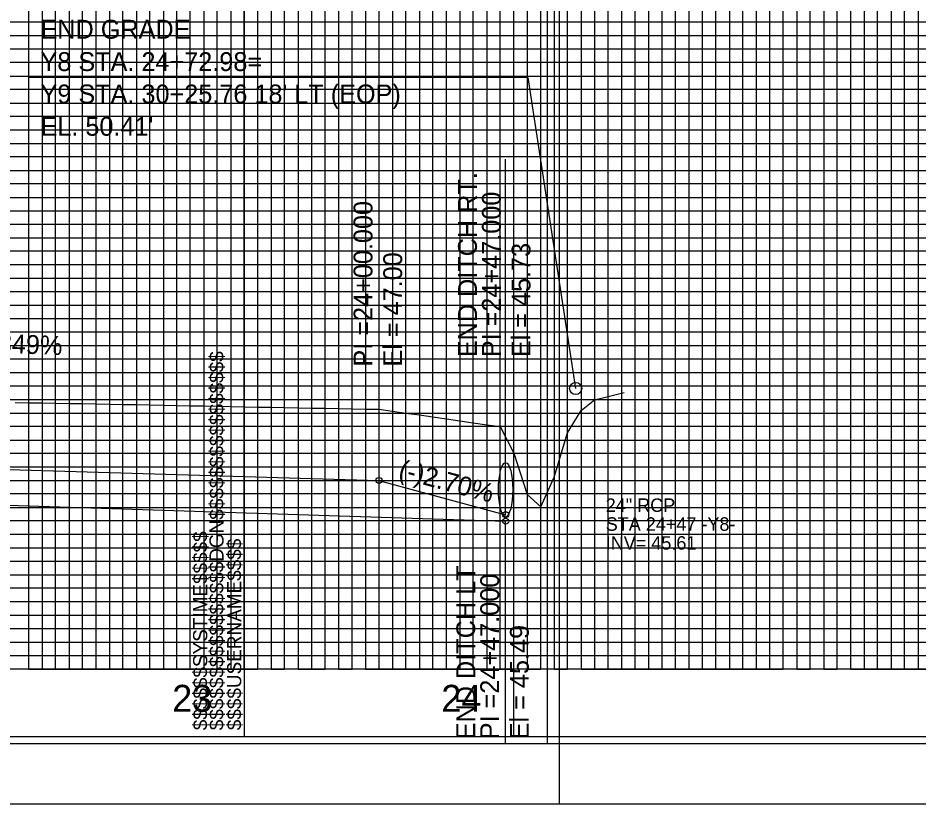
# Model space of a CAD drawing. Extents: x 2345490 to 2436403, y 465165 to 573888.
# Drawn here: x 2383032.9 to 2383366.8, y 540974.5 to 541266 of the extents above; entities that cross this region are included whole.
import ezdxf

# ---------------------------------------------------------------- set-up
doc = ezdxf.new("R2010")
doc.units = 0
for name, color, linetype in [('Exist Vertical Profile Horizontal Axis Label Major', 7, 'Continuous'), ('Old_Level_1', 7, 'Continuous'), ('Old_Level_18', 7, 'Continuous'), ('Old_Level_2', 7, 'Continuous'), ('Old_Level_3', 7, 'Continuous'), ('Old_Level_40', 7, 'Continuous'), ('Old_Level_41', 7, 'Continuous'), ('Old_Level_42', 7, 'Continuous'), ('Old_Level_43', 7, 'Continuous'), ('Old_Level_50', 7, 'Continuous'), ('Old_Level_51', 7, 'Continuous')]:
    doc.layers.add(name, color=color, linetype=linetype)

msp = doc.modelspace()

# ---------------------------------------------------------------- linework, layer by layer
at = {"layer": 'Old_Level_1'}
msp.add_lwpolyline([(2383031.7988, 541123.441), (2383036.7988, 541123.35714), (2383041.7988, 541123.27083), (2383046.7988, 541123.1821), (2383051.7988, 541123.091), (2383056.7988, 541122.99758), (2383061.7988, 541122.90186), (2383066.7988, 541122.80938), (2383071.7988, 541122.72287), (2383076.7988, 541122.63529), (2383081.7988, 541122.54668), (2383086.7988, 541122.45707), (2383091.7988, 541122.35847), (2383096.7988, 541122.23957), (2383101.7988, 541122.13262), (2383106.7988, 541122.03737), (2383111.7988, 541121.94212), (2383116.7988, 541121.84688), (2383121.7988, 541121.75163), (2383126.7988, 541121.65638), (2383131.7988, 541121.56114), (2383136.7988, 541121.46589), (2383141.7988, 541121.37064), (2383146.7988, 541121.2754), (2383151.7988, 541121.18015), (2383156.7988, 541121.0849), (2383161.7988, 541120.98965), (2383166.7988, 541120.89441), (2383171.7988, 541120.24181), (2383176.7988, 541119.51729), (2383181.7988, 541118.79276), (2383186.7988, 541118.06824), (2383191.7988, 541117.34372), (2383196.7988, 541116.61919), (2383201.7988, 541115.89467), (2383206.7988, 541115.17015), (2383211.7988, 541114.57352), (2383216.7988, 541104.6758), (2383221.7988, 541089.28992), (2383226.7988, 541084.70339), (2383231.7988, 541095.7072), (2383236.7988, 541112.14277), (2383241.7988, 541120.4894), (2383246.7988, 541124.38886), (2383251.7988, 541125.6911), (2383256.7988, 541126.94345), (2383257.7788, 541127.17918)], dxfattribs=at)
at = {"layer": 'Old_Level_18'}
msp.add_line((2383116.79875, 540999.5045), (2383116.79875, 540999.5045), dxfattribs=at)
msp.add_line((2383116.79875, 540999.5045), (2383116.79875, 540999.5045), dxfattribs=at)
for points in [[(2383216.79875, 542049.5045), (2381716.79875, 542049.5045), (2381716.79875, 540999.5045), (2383216.79875, 540999.5045)], [(2384616.79875, 542049.5045), (2383116.79875, 542049.5045), (2383116.79875, 540999.5045), (2384616.79875, 540999.5045)]]:
    msp.add_lwpolyline(points, close=True, dxfattribs=at)
at = {"layer": 'Old_Level_2'}
for q in [(2383036.88355, 541243.91325), (2383239.77875, 541128.6045)]:
    msp.add_line((2383222.04055, 541243.91325), q, dxfattribs=at)
msp.add_circle((2383239.77875, 541128.6045), 2.25, dxfattribs=at)
at = {"layer": 'Old_Level_3'}
for p, q in [((2383213.7988, 541081.8045), (2383213.7988, 541213.67542)), ((2383166.7988, 541210.1541), (2383166.7988, 541094.5045)), ((2382316.79909, 541108.4045), (2383213.7988, 541079.4045)), ((2382866.7988, 541103.5045), (2383166.7988, 541094.5045)), ((2383166.7988, 541094.5045), (2383213.7988, 541081.8045)), ((2383213.7988, 540997.24227), (2383213.7988, 541079.4045))]:
    msp.add_line(p, q, dxfattribs=at)
for centre in [(2383166.7988, 541094.5045), (2383213.7988, 541081.8045), (2383213.7988, 541079.4045)]:
    msp.add_circle(centre, 1.12602, dxfattribs=at)
msp.add_ellipse((2383213.7988, 541091.1045), major_axis=(0, -10), ratio=0.264816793, dxfattribs=at)
at = {"layer": 'Old_Level_40'}
msp.add_line((2383116.79875, 540999.5045), (2383116.79875, 540999.5045), dxfattribs=at)
msp.add_line((2383116.79875, 540999.5045), (2383116.79875, 540999.5045), dxfattribs=at)
msp.add_line((2383116.79875, 540999.5045), (2383116.79875, 540999.5045), dxfattribs=at)
msp.add_line((2383116.79875, 540999.5045), (2383116.79875, 540999.5045), dxfattribs=at)
at = {"layer": 'Old_Level_41'}
for p, q in [((2383216.79875, 541024.5045), (2381716.79875, 541024.5045)), ((2384616.79875, 541024.5045), (2383116.79875, 541024.5045))]:
    msp.add_line(p, q, dxfattribs=at)
for points in [[(2383116.79875, 542049.5045), (2383166.79875, 542049.5045), (2383166.79875, 541024.5045), (2383216.79875, 541024.5045), (2383216.79875, 542049.5045), (2383266.79875, 542049.5045), (2383266.79875, 541024.5045), (2383316.79875, 541024.5045), (2383316.79875, 542049.5045), (2383366.79875, 542049.5045), (2383366.79875, 541024.5045), (2383416.79875, 541024.5045), (2383416.79875, 542049.5045), (2383466.79875, 542049.5045), (2383466.79875, 541024.5045), (2383516.79875, 541024.5045), (2383516.79875, 542049.5045), (2383566.79875, 542049.5045), (2383566.79875, 541024.5045), (2383616.79875, 541024.5045), (2383616.79875, 542049.5045), (2383666.79875, 542049.5045), (2383666.79875, 541024.5045), (2383716.79875, 541024.5045)], [(2383191.79875, 541024.5045), (2383191.79875, 542049.5045), (2383241.79875, 542049.5045), (2383241.79875, 541024.5045), (2383291.79875, 541024.5045), (2383291.79875, 542049.5045), (2383341.79875, 542049.5045), (2383341.79875, 541024.5045), (2383391.79875, 541024.5045), (2383391.79875, 542049.5045), (2383441.79875, 542049.5045), (2383441.79875, 541024.5045), (2383491.79875, 541024.5045), (2383491.79875, 542049.5045), (2383541.79875, 542049.5045), (2383541.79875, 541024.5045), (2383591.79875, 541024.5045), (2383591.79875, 542049.5045), (2383641.79875, 542049.5045), (2383641.79875, 541024.5045), (2383691.79875, 541024.5045), (2383691.79875, 542049.5045), (2383741.79875, 542049.5045)], [(2383041.79875, 541911.9545), (2383041.79875, 541024.5045), (2383091.79875, 541024.5045), (2383091.79875, 541911.9545)], [(2383141.79875, 541911.9545), (2383141.79875, 541024.5045)], [(2383216.79875, 541249.5045), (2381716.79875, 541249.5045), (2381716.79875, 541199.5045), (2383216.79875, 541199.5045)], [(2384616.79875, 541249.5045), (2383116.79875, 541249.5045), (2383116.79875, 541199.5045), (2384616.79875, 541199.5045)], [(2383216.79875, 541149.5045), (2381716.79875, 541149.5045), (2381716.79875, 541099.5045), (2383216.79875, 541099.5045)], [(2384616.79875, 541149.5045), (2383116.79875, 541149.5045), (2383116.79875, 541099.5045), (2384616.79875, 541099.5045)], [(2383216.79875, 541074.5045), (2381716.79875, 541074.5045), (2381716.79875, 541124.5045), (2383216.79875, 541124.5045)], [(2384616.79875, 541074.5045), (2383116.79875, 541074.5045), (2383116.79875, 541124.5045), (2384616.79875, 541124.5045)], [(2383216.79875, 541049.5045), (2381716.79875, 541049.5045)], [(2384616.79875, 541049.5045), (2383116.79875, 541049.5045)], [(2383154.29875, 540999.5045), (2383154.29875, 540999.5045)]]:
    msp.add_lwpolyline(points, dxfattribs=at)
at = {"layer": 'Old_Level_42'}
for points in [[(2383066.79875, 541911.9545), (2383066.79875, 541024.5045), (2383116.79875, 541024.5045), (2383116.79875, 541911.9545)], [(2383166.79875, 541911.9545), (2383166.79875, 541024.5045), (2383216.79875, 541024.5045)], [(2383216.79875, 541174.5045), (2381716.79875, 541174.5045), (2381716.79875, 541224.5045), (2383216.79875, 541224.5045)], [(2384616.79875, 541174.5045), (2383116.79875, 541174.5045), (2383116.79875, 541224.5045), (2384616.79875, 541224.5045)]]:
    msp.add_lwpolyline(points, dxfattribs=at)
at = {"layer": 'Old_Level_43'}
for points in [[(2383171.79875, 542049.5045), (2383171.79875, 541024.5045), (2383176.79875, 541024.5045), (2383176.79875, 542049.5045)], [(2383181.79875, 542049.5045), (2383181.79875, 541024.5045), (2383186.79875, 541024.5045), (2383186.79875, 542049.5045)], [(2383196.79875, 542049.5045), (2383196.79875, 541024.5045), (2383201.79875, 541024.5045), (2383201.79875, 542049.5045)], [(2383206.79875, 542049.5045), (2383206.79875, 541024.5045), (2383211.79875, 541024.5045), (2383211.79875, 542049.5045)], [(2383221.79875, 542049.5045), (2383221.79875, 541024.5045), (2383226.79875, 541024.5045), (2383226.79875, 542049.5045)], [(2383231.79875, 542049.5045), (2383231.79875, 541024.5045), (2383236.79875, 541024.5045), (2383236.79875, 542049.5045)], [(2383246.79875, 542049.5045), (2383246.79875, 541024.5045), (2383251.79875, 541024.5045), (2383251.79875, 542049.5045)], [(2383256.79875, 542049.5045), (2383256.79875, 541024.5045), (2383261.79875, 541024.5045), (2383261.79875, 542049.5045)], [(2383271.79875, 542049.5045), (2383271.79875, 541024.5045), (2383276.79875, 541024.5045), (2383276.79875, 542049.5045)], [(2383281.79875, 542049.5045), (2383281.79875, 541024.5045), (2383286.79875, 541024.5045), (2383286.79875, 542049.5045)], [(2383296.79875, 542049.5045), (2383296.79875, 541024.5045), (2383301.79875, 541024.5045), (2383301.79875, 542049.5045)], [(2383306.79875, 542049.5045), (2383306.79875, 541024.5045), (2383311.79875, 541024.5045), (2383311.79875, 542049.5045)], [(2383321.79875, 542049.5045), (2383321.79875, 541024.5045), (2383326.79875, 541024.5045), (2383326.79875, 542049.5045)], [(2383331.79875, 541024.5045), (2383336.79875, 541024.5045), (2383336.79875, 542049.5045)], [(2383331.79875, 542049.5045), (2383331.79875, 541024.5045)], [(2383346.79875, 542049.5045), (2383346.79875, 541024.5045), (2383351.79875, 541024.5045), (2383351.79875, 542049.5045)], [(2383356.79875, 542049.5045), (2383356.79875, 541024.5045), (2383361.79875, 541024.5045), (2383361.79875, 542049.5045)], [(2383036.79875, 541911.9545), (2383036.79875, 541024.5045), (2383046.79875, 541024.5045), (2383046.79875, 541911.9545)], [(2383051.79875, 541911.9545), (2383051.79875, 541024.5045), (2383056.79875, 541024.5045), (2383056.79875, 541911.9545)], [(2383061.79875, 541911.9545), (2383061.79875, 541024.5045), (2383071.79875, 541024.5045), (2383071.79875, 541911.9545)], [(2383076.79875, 541911.9545), (2383076.79875, 541024.5045), (2383081.79875, 541024.5045), (2383081.79875, 541911.9545)], [(2383086.79875, 541911.9545), (2383086.79875, 541024.5045), (2383096.79875, 541024.5045), (2383096.79875, 541911.9545)], [(2383101.79875, 541911.9545), (2383101.79875, 541024.5045)], [(2383101.79875, 541024.5045), (2383106.79875, 541024.5045), (2383106.79875, 541911.9545)], [(2383111.79875, 541911.9545), (2383111.79875, 541024.5045), (2383121.79875, 541024.5045), (2383121.79875, 541911.9545)], [(2383126.79875, 541911.9545), (2383126.79875, 541024.5045), (2383131.79875, 541024.5045), (2383131.79875, 541911.9545)], [(2383136.79875, 541911.9545), (2383136.79875, 541024.5045), (2383146.79875, 541024.5045), (2383146.79875, 541911.9545)], [(2383151.79875, 541911.9545), (2383151.79875, 541024.5045), (2383156.79875, 541024.5045), (2383156.79875, 541911.9545)], [(2383161.79875, 541911.9545), (2383161.79875, 541024.5045), (2383171.79875, 541024.5045)], [(2383166.79875, 541264.5045), (2381766.79875, 541264.5045), (2381766.79875, 541259.5045), (2383166.79875, 541259.5045)], [(2384566.79875, 541264.5045), (2383166.79875, 541264.5045), (2383166.79875, 541259.5045), (2384566.79875, 541259.5045)], [(2383166.79875, 541254.5045), (2381766.79875, 541254.5045), (2381766.79875, 541244.5045), (2383166.79875, 541244.5045)], [(2384566.79875, 541254.5045), (2383166.79875, 541254.5045), (2383166.79875, 541244.5045), (2384566.79875, 541244.5045)], [(2383166.79875, 541239.5045), (2381766.79875, 541239.5045), (2381766.79875, 541234.5045), (2383166.79875, 541234.5045)], [(2384566.79875, 541239.5045), (2383166.79875, 541239.5045), (2383166.79875, 541234.5045), (2384566.79875, 541234.5045)], [(2383166.79875, 541229.5045), (2381766.79875, 541229.5045)], [(2384566.79875, 541229.5045), (2383166.79875, 541229.5045)], [(2381766.79875, 541219.5045), (2383166.79875, 541219.5045)], [(2383166.79875, 541219.5045), (2384566.79875, 541219.5045)], [(2383166.79875, 541214.5045), (2381766.79875, 541214.5045), (2381766.79875, 541209.5045), (2383166.79875, 541209.5045)], [(2384566.79875, 541214.5045), (2383166.79875, 541214.5045), (2383166.79875, 541209.5045), (2384566.79875, 541209.5045)], [(2383166.79875, 541204.5045), (2381766.79875, 541204.5045)], [(2384566.79875, 541204.5045), (2383166.79875, 541204.5045)], [(2381766.79875, 541194.5045), (2383166.79875, 541194.5045)], [(2383166.79875, 541194.5045), (2384566.79875, 541194.5045)], [(2383166.79875, 541189.5045), (2381766.79875, 541189.5045), (2381766.79875, 541184.5045), (2383166.79875, 541184.5045)], [(2384566.79875, 541189.5045), (2383166.79875, 541189.5045), (2383166.79875, 541184.5045), (2384566.79875, 541184.5045)], [(2383166.79875, 541179.5045), (2381766.79875, 541179.5045), (2381766.79875, 541169.5045), (2383166.79875, 541169.5045)], [(2384566.79875, 541179.5045), (2383166.79875, 541179.5045), (2383166.79875, 541169.5045), (2384566.79875, 541169.5045)], [(2383166.79875, 541164.5045), (2381766.79875, 541164.5045), (2381766.79875, 541159.5045), (2383166.79875, 541159.5045)], [(2384566.79875, 541164.5045), (2383166.79875, 541164.5045), (2383166.79875, 541159.5045), (2384566.79875, 541159.5045)], [(2383166.79875, 541154.5045), (2381766.79875, 541154.5045), (2381766.79875, 541144.5045), (2383166.79875, 541144.5045)], [(2384566.79875, 541154.5045), (2383166.79875, 541154.5045), (2383166.79875, 541144.5045), (2384566.79875, 541144.5045)], [(2383166.79875, 541139.5045), (2381766.79875, 541139.5045), (2381766.79875, 541134.5045), (2383166.79875, 541134.5045)], [(2384566.79875, 541139.5045), (2383166.79875, 541139.5045), (2383166.79875, 541134.5045), (2384566.79875, 541134.5045)], [(2383166.79875, 541129.5045), (2381766.79875, 541129.5045), (2381766.79875, 541119.5045), (2383166.79875, 541119.5045)], [(2384566.79875, 541129.5045), (2383166.79875, 541129.5045), (2383166.79875, 541119.5045), (2384566.79875, 541119.5045)], [(2383166.79875, 541114.5045), (2381766.79875, 541114.5045), (2381766.79875, 541109.5045), (2383166.79875, 541109.5045)], [(2384566.79875, 541114.5045), (2383166.79875, 541114.5045), (2383166.79875, 541109.5045), (2384566.79875, 541109.5045)], [(2383166.79875, 541104.5045), (2381766.79875, 541104.5045), (2381766.79875, 541094.5045), (2383166.79875, 541094.5045)], [(2384566.79875, 541104.5045), (2383166.79875, 541104.5045), (2383166.79875, 541094.5045), (2384566.79875, 541094.5045)], [(2383166.79875, 541089.5045), (2381766.79875, 541089.5045), (2381766.79875, 541084.5045), (2383166.79875, 541084.5045)], [(2384566.79875, 541089.5045), (2383166.79875, 541089.5045), (2383166.79875, 541084.5045), (2384566.79875, 541084.5045)], [(2383166.79875, 541079.5045), (2381766.79875, 541079.5045), (2381766.79875, 541069.5045), (2383166.79875, 541069.5045)], [(2384566.79875, 541079.5045), (2383166.79875, 541079.5045), (2383166.79875, 541069.5045), (2384566.79875, 541069.5045)], [(2383166.79875, 541064.5045), (2381766.79875, 541064.5045), (2381766.79875, 541059.5045), (2383166.79875, 541059.5045)], [(2384566.79875, 541064.5045), (2383166.79875, 541064.5045), (2383166.79875, 541059.5045), (2384566.79875, 541059.5045)], [(2383166.79875, 541054.5045), (2381766.79875, 541054.5045), (2381766.79875, 541044.5045), (2383166.79875, 541044.5045)], [(2384566.79875, 541054.5045), (2383166.79875, 541054.5045), (2383166.79875, 541044.5045), (2384566.79875, 541044.5045)], [(2383166.79875, 541039.5045), (2381766.79875, 541039.5045), (2381766.79875, 541034.5045), (2383166.79875, 541034.5045)], [(2384566.79875, 541039.5045), (2383166.79875, 541039.5045), (2383166.79875, 541034.5045), (2384566.79875, 541034.5045)], [(2383166.79875, 541029.5045), (2381766.79875, 541029.5045)], [(2384566.79875, 541029.5045), (2383166.79875, 541029.5045)]]:
    msp.add_lwpolyline(points, dxfattribs=at)
at = {"layer": 'Old_Level_50'}
for points in [[(2383229.29875, 542052.0545), (2381562.79875, 542052.0545), (2381562.79875, 540996.9545), (2383229.29875, 540996.9545)], [(2384629.29875, 542052.0545), (2382962.79875, 542052.0545), (2382962.79875, 540996.9545), (2384629.29875, 540996.9545)]]:
    msp.add_lwpolyline(points, close=True, dxfattribs=at)
at = {"layer": 'Old_Level_51'}
for points in [[(2383233.79875, 542074.5045), (2381549.79875, 542074.5045), (2381549.79875, 540974.5045), (2383233.79875, 540974.5045)], [(2384633.79875, 542074.5045), (2382949.79875, 542074.5045), (2382949.79875, 540974.5045), (2384633.79875, 540974.5045)]]:
    msp.add_lwpolyline(points, close=True, dxfattribs=at)

# ---------------------------------------------------------------- texts
at = {"layer": 'Exist Vertical Profile Horizontal Axis Label Major'}
for s, p in [('23', (2383090.09389, 541008.69864)), ('24', (2383189.93631, 541008.69864))]:
    msp.add_text(s, height=10.000001, dxfattribs=at).set_placement(p)
at = {"layer": 'Old_Level_2'}
for s, height, p in [('END GRADE', 7.000001, (2383041.2238, 541258.36625)), ('Y8 STA. 24+72.98=', 7.0000005, (2383041.2238, 541246.36625)), ("Y9 STA. 30+25.76 18' LT (EOP)", 7.0000005, (2383041.2238, 541234.36625)), ("EL. 50.41' ", 7.0000005, (2383041.2238, 541222.36625))]:
    msp.add_text(s, height=height, dxfattribs=at).set_placement(p)
msp.add_text('(-)0.3849%', height=7, rotation=357.7471697, dxfattribs=at).set_placement((2383002.94472, 541142.81846))
at = {"layer": 'Old_Level_3'}
for s, height, rotation, p in [('END DITCH RT.', 7.0000005, 90, (2383203.14605, 541140.21463)), ('PI =24+47.000', 7.0000005, 90, (2383212.01995, 541140.21463)), ('PI =24+00.000', 7.0000005, 90, (2383164.3938, 541136.7485)), ('El = 45.73', 7.000001, 90, (2383223.01995, 541140.21463)), ('El = 47.00', 7.000001, 90, (2383175.3938, 541136.7485)), ('(-)2.70%', 7.000001, 344.8790632, (2383173.65627, 541095.56937)), ('END DITCH LT', 7.0000005, 90, (2383202.5199, 540998.50801)), ('PI =24+47.000', 7.0000005, 90, (2383211.3938, 540998.50801)), ('El = 45.49', 7.000001, 90, (2383222.3938, 540998.50801))]:
    msp.add_text(s, height=height, rotation=rotation, dxfattribs=at).set_placement(p)
for s, height, p in [('24" RCP', 4.999999, (2383250.93388, 541082.8386)), ('STA 24+47 -Y8-', 4.9999995, (2383250.93388, 541075.8386)), ('INV= 45.61', 4.999999, (2383250.93388, 541068.83861))]:
    msp.add_text(s, height=height, dxfattribs=at).set_placement(p)
at = {"layer": 'Old_Level_41'}
for s, p in [('$$$$$$$$$$$$$$$$DGN$$$$$$$$$$$$$$$$', (2383109.14875, 541001.867)), ('$$$$$$SYSTIME$$$$$', (2383103.09875, 541001.867)), ('$$$$USERNAME$$$$', (2383115.72375, 541001.8795))]:
    msp.add_text(s, height=5.25, rotation=90, dxfattribs=at).set_placement(p)

doc.saveas('drawing.dxf')
